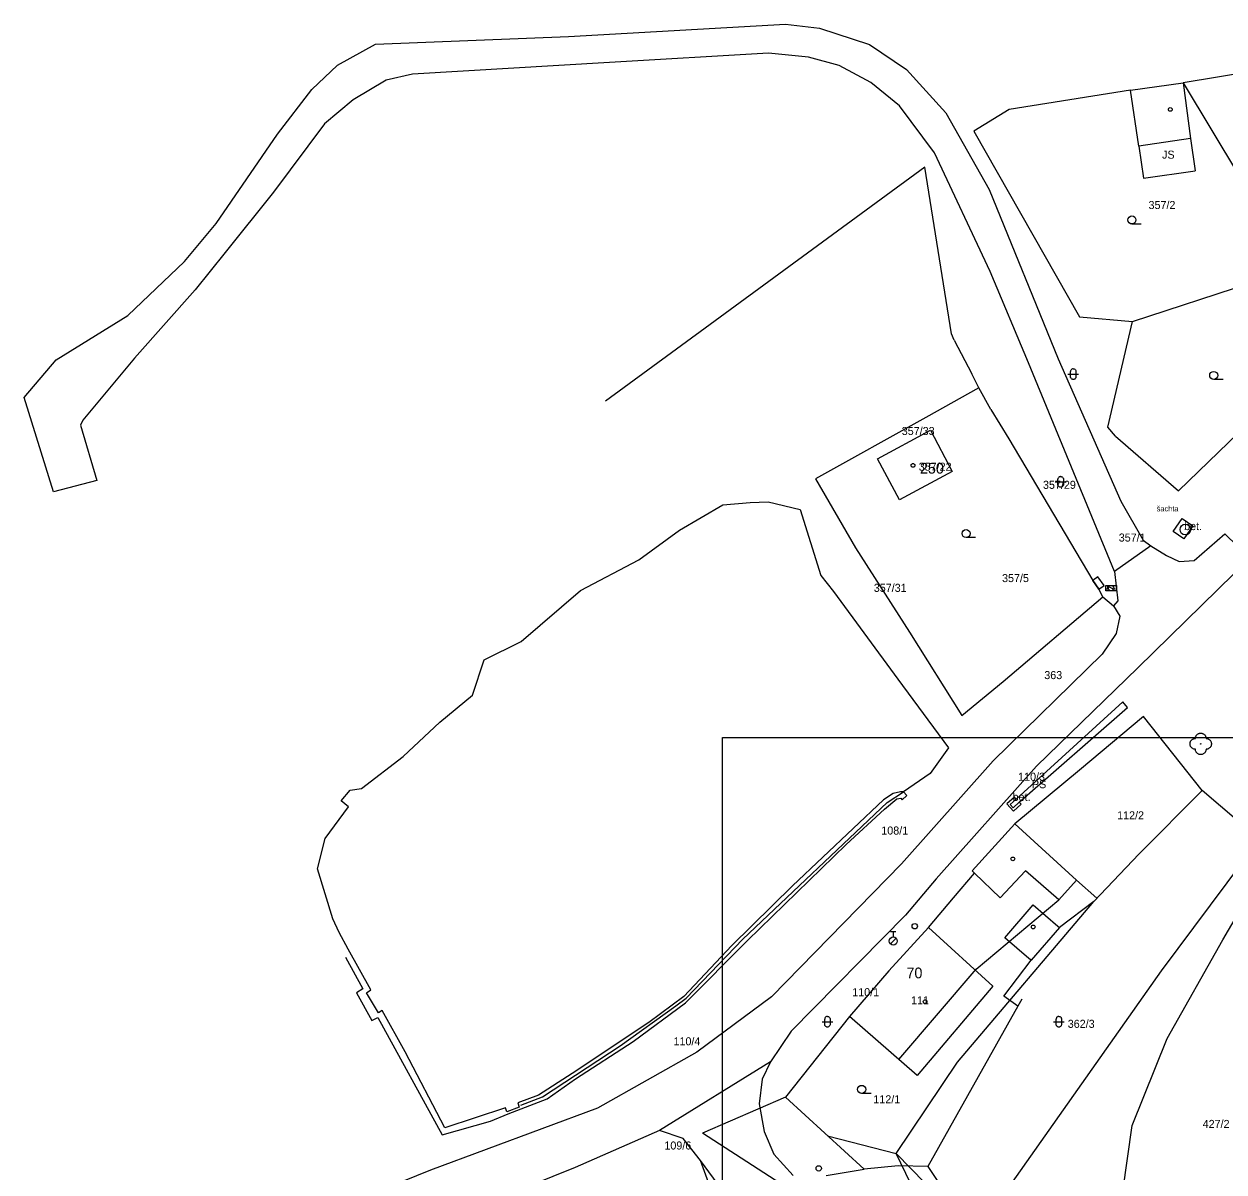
# Model space of a CAD drawing. Extents: x -836615 to -835459, y -1070675 to -1070205.
# Drawn here: x -836568.3 to -836456.3, y -1070319.2 to -1070212.1 of the extents above; entities that cross this region are included whole.
import ezdxf

# ---------------------------------------------------------------- set-up
doc = ezdxf.new("R2010")
doc.units = 0
for name, color, linetype in [('BodPole_body', 7, 'Continuous'), ('Budovy_hranice', 7, 'Continuous'), ('Budovy_kody', 7, 'Continuous'), ('Doprava_hranice', 7, 'Continuous'), ('OstPloch_hranice', 7, 'Continuous'), ('OstPloch_kody', 7, 'Continuous'), ('PovrZnIS_body', 7, 'Continuous'), ('PovrZnIS_hranice', 7, 'Continuous'), ('RuianAdr_popis', 7, 'Continuous'), ('RuianPar_popis', 7, 'Continuous'), ('Stavby_hr_stav', 7, 'Continuous'), ('Stavby_kody', 7, 'Continuous'), ('Stavby_linie', 7, 'Continuous'), ('Stavby_popis', 7, 'Continuous'), ('Vodstvo_hranice', 7, 'Continuous'), ('Zelen_body', 7, 'Continuous')]:
    doc.layers.add(name, color=color, linetype=linetype)

msp = doc.modelspace()

# ---------------------------------------------------------------- linework, layer by layer
at = {"layer": 'BodPole_body'}
msp.add_lwpolyline([(-836503.12, -1070278.67), (-836206.12, -1070278.67), (-836206.12, -1070488.67), (-836503.12, -1070488.67)], close=True, dxfattribs=at)
at = {"layer": 'Budovy_hranice'}
for p, q in [((-836475.84, -1070286.72), (-836479.82, -1070291.11)), ((-836487.6, -1070300.42), (-836491.27, -1070304.7))]:
    msp.add_line(p, q, dxfattribs=at)
for points in [[(-836460.13, -1070217.59), (-836459.42, -1070222.78), (-836464.25, -1070223.5), (-836465.02, -1070218.27), (-836460.13, -1070217.59)], [(-836481.66, -1070253.86), (-836486.58, -1070256.5), (-836488.64, -1070252.68), (-836483.69, -1070250.01), (-836481.66, -1070253.86)], [(-836475.84, -1070286.72), (-836470.06, -1070291.96), (-836471.71, -1070293.81), (-836474.82, -1070291.1), (-836477.18, -1070293.62), (-836479.59, -1070291.33), (-836479.82, -1070291.11)], [(-836474.31, -1070299.45), (-836474.52, -1070299.27), (-836476.76, -1070297.35), (-836474.12, -1070294.28), (-836471.8, -1070296.28), (-836471.67, -1070296.39), (-836474.31, -1070299.45)], [(-836487.6, -1070300.42), (-836483.87, -1070296.4), (-836477.87, -1070301.86), (-836484.93, -1070310.21), (-836491.27, -1070304.7)]]:
    msp.add_lwpolyline(points, dxfattribs=at)
at = {"layer": 'Budovy_kody'}
for p, q in [((-836470.06, -1070291.96), (-836468.16, -1070293.65)), ((-836497.22, -1070312.21), (-836504.98, -1070315.57))]:
    msp.add_line(p, q, dxfattribs=at)
for points in [[(-836493.32, -1070315.82), (-836486.89, -1070317.46), (-836481.18, -1070308.95), (-836468.46, -1070293.96)], [(-836428.56, -1070366.77), (-836395.84, -1070391.08), (-836420.45, -1070375.43), (-836435.19, -1070364.96), (-836454.22, -1070349.64), (-836469.26, -1070337.57), (-836482.9, -1070325.77), (-836486.89, -1070317.46), (-836480.18, -1070324.33), (-836464.23, -1070338.22), (-836436.21, -1070293.95), (-836419.72, -1070300.08)], [(-836486.64, -1070308.7), (-836479.43, -1070300.28), (-836471.71, -1070293.81)], [(-836395.84, -1070391.08), (-836432.08, -1070371.33), (-836463.95, -1070348.14), (-836486.49, -1070329.05), (-836494.06, -1070322.64), (-836504.98, -1070315.57)]]:
    msp.add_lwpolyline(points, dxfattribs=at)
for centre in [(-836461.32, -1070220.08), (-836485.33, -1070253.28), (-836476.01, -1070289.99), (-836474.11, -1070296.34), (-836484.2, -1070303.31)]:
    msp.add_circle(centre, 0.175, dxfattribs=at)
at = {"layer": 'Doprava_hranice'}
for points in [[(-836565.55, -1070255.75), (-836568.29, -1070246.94), (-836565.3, -1070243.45), (-836558.59, -1070239.29), (-836553.32, -1070234.26), (-836550.36, -1070230.73), (-836544.63, -1070222.38), (-836541.42, -1070218.21), (-836539.02, -1070215.95), (-836535.5, -1070213.99), (-836517.48, -1070213.29), (-836497.22, -1070212.11), (-836494.05, -1070212.5), (-836489.39, -1070214.02), (-836485.93, -1070216.36), (-836482.28, -1070220.4), (-836478.23, -1070227.56), (-836471.79, -1070243.33), (-836465.92, -1070256.62), (-836463.85, -1070260.25), (-836463.13, -1070260.78)], [(-836466.54, -1070263.19), (-836474.56, -1070243.73), (-836478.12, -1070235.21), (-836483.33, -1070224.14), (-836486.58, -1070219.75), (-836489.27, -1070217.57), (-836492.22, -1070215.97), (-836495.08, -1070215.2), (-836498.82, -1070214.84), (-836513.64, -1070215.7), (-836532.05, -1070216.8), (-836534.5, -1070217.36), (-836537.57, -1070219.18), (-836540.24, -1070221.43), (-836545, -1070227.8), (-836549.52, -1070233.43), (-836552.32, -1070236.92), (-836557.98, -1070243.27), (-836562.8, -1070249.08), (-836563.01, -1070249.54), (-836561.48, -1070254.69), (-836565.55, -1070255.75)], [(-836463.13, -1070260.78), (-836461.66, -1070261.68), (-836460.5, -1070262.24), (-836459.09, -1070262.17), (-836456.22, -1070259.67), (-836453.89, -1070261.93), (-836464.34, -1070272.16), (-836473.79, -1070281.33)], [(-836463.13, -1070260.78), (-836466.54, -1070263.19), (-836466.2, -1070265.91), (-836466.63, -1070266.39), (-836466.02, -1070267.34), (-836466.37, -1070268.96), (-836467.68, -1070270.88), (-836477.85, -1070280.85), (-836486.39, -1070290.44)], [(-836473.79, -1070281.33), (-836483.18, -1070291.85), (-836486.04, -1070295.25), (-836496.69, -1070306.07), (-836498.64, -1070308.92), (-836508.98, -1070315.34), (-836516.87, -1070318.79), (-836525.05, -1070322.08), (-836528.75, -1070323.23)], [(-836486.39, -1070290.44), (-836498.54, -1070302.85), (-836505.49, -1070308.01), (-836514.78, -1070313.23), (-836530.36, -1070319.04), (-836537.03, -1070321.73), (-836555.38, -1070326.29), (-836561.14, -1070327.96), (-836562.04, -1070328.06)], [(-836498.64, -1070308.92), (-836499.4, -1070310.53), (-836499.69, -1070312.83), (-836499.23, -1070315.41), (-836498.31, -1070317.53), (-836496.52, -1070319.54)], [(-836536.4, -1070368.21), (-836533.17, -1070355.68), (-836529.95, -1070350.14), (-836526.64, -1070346.09), (-836522.06, -1070342.08), (-836518.27, -1070339.72), (-836511.7, -1070337.08), (-836507.28, -1070334.68), (-836504.64, -1070331.81), (-836503.25, -1070329.28), (-836502.09, -1070325.77), (-836501.89, -1070323.62), (-836502.72, -1070321.42), (-836505.15, -1070318.12), (-836506.77, -1070316.06), (-836508.98, -1070315.34)], [(-836541.58, -1070350.39), (-836544.34, -1070349.63), (-836547.79, -1070346.93), (-836549.07, -1070344.38), (-836548.75, -1070338.43), (-836546.32, -1070335.63), (-836537.04, -1070331.76), (-836528.76, -1070329.97), (-836518.57, -1070326.72), (-836515.72, -1070324.62), (-836506.05, -1070328.35), (-836503.77, -1070324.55), (-836503.82, -1070321.79), (-836505.15, -1070318.12)]]:
    msp.add_lwpolyline(points, dxfattribs=at)
at = {"layer": 'OstPloch_hranice'}
for p, q in [((-836467.63, -1070265.54), (-836466.63, -1070266.39)), ((-836493.44, -1070319.52), (-836489.89, -1070318.94))]:
    msp.add_line(p, q, dxfattribs=at)
for points in [[(-836459.22, -1070258.92), (-836460.06, -1070260.14), (-836461.05, -1070259.46), (-836460.21, -1070258.24), (-836459.22, -1070258.92)], [(-836356.62, -1070406.87), (-836370.19, -1070399.44), (-836385.43, -1070392.2), (-836396.38, -1070386.03), (-836404.41, -1070381.11), (-836409.87, -1070376.61), (-836425.28, -1070363.93), (-836449.03, -1070345.44), (-836455, -1070340), (-836462.64, -1070329.11), (-836464.81, -1070325.47), (-836465.74, -1070321.03), (-836464.89, -1070314.87), (-836461.62, -1070306.74), (-836456.41, -1070297.54), (-836450.95, -1070288.2), (-836447.03, -1070272.79), (-836441.38, -1070260.76)]]:
    msp.add_lwpolyline(points, dxfattribs=at)
at = {"layer": 'OstPloch_kody'}
for p, q in [((-836464.03, -1070230.77), (-836464.9, -1070230.77)), ((-836470.62, -1070245.02), (-836470.62, -1070244.52)), ((-836470.12, -1070244.52), (-836470.12, -1070245.02)), ((-836470.87, -1070244.77), (-836469.87, -1070244.77)), ((-836456.4, -1070245.27), (-836457.27, -1070245.27)), ((-836472.05, -1070254.82), (-836471.05, -1070254.82)), ((-836471.8, -1070255.07), (-836471.8, -1070254.57)), ((-836471.3, -1070254.57), (-836471.3, -1070255.07)), ((-836479.51, -1070260.02), (-836480.38, -1070260.02)), ((-836493.82, -1070305.18), (-836492.82, -1070305.18)), ((-836493.57, -1070305.43), (-836493.57, -1070304.93)), ((-836493.07, -1070304.93), (-836493.07, -1070305.43)), ((-836472.22, -1070305.18), (-836471.22, -1070305.18)), ((-836471.97, -1070305.43), (-836471.97, -1070304.93)), ((-836471.47, -1070304.93), (-836471.47, -1070305.43)), ((-836489.24, -1070311.87), (-836490.12, -1070311.87))]:
    msp.add_line(p, q, dxfattribs=at)
for points in [[(-836470.37, -1070244.27), (-836470.42, -1070244.27), (-836470.46, -1070244.29), (-836470.51, -1070244.31), (-836470.55, -1070244.34), (-836470.58, -1070244.38), (-836470.6, -1070244.43), (-836470.62, -1070244.47), (-836470.62, -1070244.52)], [(-836470.37, -1070244.27), (-836470.32, -1070244.27), (-836470.28, -1070244.29), (-836470.23, -1070244.31), (-836470.19, -1070244.34), (-836470.16, -1070244.38), (-836470.14, -1070244.43), (-836470.12, -1070244.47), (-836470.12, -1070244.52)], [(-836470.37, -1070245.27), (-836470.42, -1070245.27), (-836470.46, -1070245.25), (-836470.51, -1070245.23), (-836470.55, -1070245.2), (-836470.58, -1070245.16), (-836470.6, -1070245.11), (-836470.62, -1070245.07), (-836470.62, -1070245.02)], [(-836470.12, -1070245.02), (-836470.12, -1070245.07), (-836470.14, -1070245.11), (-836470.16, -1070245.16), (-836470.19, -1070245.2), (-836470.23, -1070245.23), (-836470.28, -1070245.25), (-836470.32, -1070245.27), (-836470.37, -1070245.27)], [(-836471.55, -1070254.32), (-836471.6, -1070254.32), (-836471.64, -1070254.34), (-836471.69, -1070254.36), (-836471.73, -1070254.39), (-836471.76, -1070254.43), (-836471.78, -1070254.48), (-836471.8, -1070254.52), (-836471.8, -1070254.57)], [(-836471.55, -1070254.32), (-836471.5, -1070254.32), (-836471.46, -1070254.34), (-836471.41, -1070254.36), (-836471.37, -1070254.39), (-836471.34, -1070254.43), (-836471.32, -1070254.48), (-836471.3, -1070254.52), (-836471.3, -1070254.57)], [(-836471.55, -1070255.32), (-836471.6, -1070255.32), (-836471.64, -1070255.3), (-836471.69, -1070255.28), (-836471.73, -1070255.25), (-836471.76, -1070255.21), (-836471.78, -1070255.16), (-836471.8, -1070255.12), (-836471.8, -1070255.07)], [(-836471.3, -1070255.07), (-836471.3, -1070255.12), (-836471.32, -1070255.16), (-836471.34, -1070255.21), (-836471.37, -1070255.25), (-836471.41, -1070255.28), (-836471.46, -1070255.3), (-836471.5, -1070255.32), (-836471.55, -1070255.32)], [(-836493.32, -1070304.68), (-836493.37, -1070304.68), (-836493.41, -1070304.7), (-836493.46, -1070304.72), (-836493.5, -1070304.75), (-836493.53, -1070304.79), (-836493.55, -1070304.84), (-836493.57, -1070304.88), (-836493.57, -1070304.93)], [(-836493.32, -1070304.68), (-836493.27, -1070304.68), (-836493.23, -1070304.7), (-836493.18, -1070304.72), (-836493.14, -1070304.75), (-836493.11, -1070304.79), (-836493.09, -1070304.84), (-836493.07, -1070304.88), (-836493.07, -1070304.93)], [(-836471.72, -1070304.68), (-836471.77, -1070304.68), (-836471.81, -1070304.7), (-836471.86, -1070304.72), (-836471.9, -1070304.75), (-836471.93, -1070304.79), (-836471.95, -1070304.84), (-836471.97, -1070304.88), (-836471.97, -1070304.93)], [(-836471.72, -1070304.68), (-836471.67, -1070304.68), (-836471.63, -1070304.7), (-836471.58, -1070304.72), (-836471.54, -1070304.75), (-836471.51, -1070304.79), (-836471.49, -1070304.84), (-836471.47, -1070304.88), (-836471.47, -1070304.93)], [(-836493.32, -1070305.68), (-836493.37, -1070305.68), (-836493.41, -1070305.66), (-836493.46, -1070305.64), (-836493.5, -1070305.61), (-836493.53, -1070305.57), (-836493.55, -1070305.52), (-836493.57, -1070305.48), (-836493.57, -1070305.43)], [(-836493.07, -1070305.43), (-836493.07, -1070305.48), (-836493.09, -1070305.52), (-836493.11, -1070305.57), (-836493.14, -1070305.61), (-836493.18, -1070305.64), (-836493.23, -1070305.66), (-836493.27, -1070305.68), (-836493.32, -1070305.68)], [(-836471.72, -1070305.68), (-836471.77, -1070305.68), (-836471.81, -1070305.66), (-836471.86, -1070305.64), (-836471.9, -1070305.61), (-836471.93, -1070305.57), (-836471.95, -1070305.52), (-836471.97, -1070305.48), (-836471.97, -1070305.43)], [(-836471.47, -1070305.43), (-836471.47, -1070305.48), (-836471.49, -1070305.52), (-836471.51, -1070305.57), (-836471.54, -1070305.61), (-836471.58, -1070305.64), (-836471.63, -1070305.66), (-836471.67, -1070305.68), (-836471.72, -1070305.68)]]:
    msp.add_lwpolyline(points, dxfattribs=at)
for centre in [(-836464.9, -1070230.39), (-836457.27, -1070244.89), (-836480.38, -1070259.64), (-836490.12, -1070311.49)]:
    msp.add_ellipse(centre, major_axis=(0.375, 0), ratio=0.999999, dxfattribs=at)
at = {"layer": 'PovrZnIS_body'}
for p, q in [((-836467.35, -1070264.98), (-836467.35, -1070264.48)), ((-836467.35, -1070264.48), (-836466.35, -1070264.48)), ((-836467.27, -1070264.81), (-836467.16, -1070264.81)), ((-836467.16, -1070264.81), (-836467.16, -1070264.56)), ((-836467.16, -1070264.56), (-836466.66, -1070264.81)), ((-836466.66, -1070264.81), (-836466.42, -1070264.81)), ((-836466.35, -1070264.48), (-836466.35, -1070264.98)), ((-836466.35, -1070264.98), (-836467.35, -1070264.98)), ((-836487.42, -1070296.77), (-836486.92, -1070296.77)), ((-836487.17, -1070296.77), (-836487.17, -1070297.27)), ((-836486.9, -1070297.38), (-836487.44, -1070297.92))]:
    msp.add_line(p, q, dxfattribs=at)
for centre, radius in [((-836459.91, -1070259.27), 0.5), ((-836466.85, -1070264.73), 0.25), ((-836485.17, -1070296.27), 0.25), ((-836487.17, -1070297.65), 0.375), ((-836494.13, -1070318.86), 0.25)]:
    msp.add_circle(centre, radius, dxfattribs=at)
at = {"layer": 'PovrZnIS_hranice'}
msp.add_lwpolyline([(-836467.99, -1070264.84), (-836467.5, -1070264.5), (-836468.07, -1070263.68), (-836468.56, -1070264.02), (-836467.99, -1070264.84)], dxfattribs=at)
at = {"layer": 'Stavby_hr_stav'}
msp.add_line((-836459.42, -1070222.78), (-836459, -1070225.8), dxfattribs=at)
for points in [[(-836464.25, -1070223.5), (-836463.81, -1070226.48), (-836459, -1070225.8)], [(-836475.41, -1070284.71), (-836465.3, -1070275.87), (-836465.76, -1070275.33), (-836475.69, -1070284.41)], [(-836475.86, -1070284.22), (-836476.56, -1070284.86), (-836475.94, -1070285.54), (-836475.24, -1070284.9), (-836475.41, -1070284.71), (-836475.98, -1070285.22), (-836476.25, -1070284.92), (-836475.69, -1070284.41), (-836475.86, -1070284.22)]]:
    msp.add_lwpolyline(points, dxfattribs=at)
at = {"layer": 'Stavby_linie'}
for p, q in [((-836464.85, -1070239.86), (-836449.69, -1070234.92)), ((-836469.78, -1070239.43), (-836464.85, -1070239.86)), ((-836481.49, -1070241.59), (-836479.85, -1070244.75)), ((-836479.18, -1070246.06), (-836484.13, -1070248.82)), ((-836478.06, -1070248.07), (-836476.39, -1070250.81)), ((-836476.39, -1070250.81), (-836468.56, -1070264.02)), ((-836466.44, -1070250.56), (-836460.54, -1070255.66)), ((-836463.82, -1070276.71), (-836469.8, -1070281.7)), ((-836458.36, -1070283.6), (-836463.82, -1070276.71)), ((-836469.8, -1070281.7), (-836475.84, -1070286.72)), ((-836481.56, -1070293.61), (-836479.59, -1070291.33)), ((-836483.87, -1070296.4), (-836481.56, -1070293.61)), ((-836476.86, -1070302.79), (-836474.31, -1070299.45)), ((-836475.56, -1070303.74), (-836476.86, -1070302.79))]:
    msp.add_line(p, q, dxfattribs=at)
for points in [[(-836439.81, -1070215.21), (-836443.91, -1070214.91), (-836460.13, -1070217.59), (-836449.69, -1070234.92)], [(-836465.02, -1070218.27), (-836476.36, -1070220.08), (-836479.66, -1070222.11), (-836469.78, -1070239.43)], [(-836481.49, -1070241.59), (-836481.74, -1070241), (-836484.22, -1070225.45), (-836507.86, -1070242.77), (-836514.01, -1070247.28)], [(-836460.54, -1070255.66), (-836450.32, -1070245.76), (-836439.91, -1070235.75)], [(-836466.44, -1070250.56), (-836467.14, -1070249.72), (-836464.85, -1070239.86)], [(-836478.06, -1070248.07), (-836479.18, -1070246.06), (-836479.85, -1070244.75)], [(-836484.13, -1070248.82), (-836494.44, -1070254.55), (-836490.71, -1070260.96)], [(-836490.71, -1070260.96), (-836485.67, -1070268.85), (-836480.77, -1070276.62), (-836476.92, -1070273.45)], [(-836476.92, -1070273.45), (-836467.63, -1070265.54), (-836467.99, -1070264.84), (-836468.56, -1070264.02)], [(-836521.92, -1070312.95), (-836519.9, -1070312.2), (-836512.67, -1070307.44), (-836507.45, -1070303.71), (-836506.51, -1070302.98), (-836501.2, -1070297.48), (-836487.74, -1070284.74), (-836486.21, -1070283.75)], [(-836483.95, -1070318.68), (-836480.18, -1070324.33), (-836477.38, -1070322.05), (-836462.13, -1070300.43), (-836452.98, -1070288.18), (-836458.36, -1070283.6)], [(-836458.36, -1070283.6), (-836464.21, -1070289.51), (-836468.46, -1070293.96), (-836471.67, -1070296.39)], [(-836475.18, -1070303.07), (-836475.56, -1070303.74), (-836483.95, -1070318.68)], [(-836491.27, -1070304.7), (-836497.22, -1070312.21), (-836489.89, -1070318.94)], [(-836483.95, -1070318.68), (-836486.71, -1070318.63), (-836489.89, -1070318.94)]]:
    msp.add_lwpolyline(points, dxfattribs=at)
at = {"layer": 'Vodstvo_hranice'}
for points in [[(-836486.21, -1070283.75), (-836486.51, -1070283.72), (-836487.17, -1070283.89), (-836488.08, -1070284.48), (-836496.59, -1070292.51), (-836502.23, -1070298.08), (-836506.71, -1070302.82), (-836509.99, -1070305.26), (-836517.14, -1070310.02), (-836520.29, -1070312.03), (-836522.22, -1070312.76), (-836522.07, -1070313.16), (-836523.23, -1070313.58), (-836523.35, -1070313.2), (-836529.02, -1070315.07), (-836532.73, -1070307.98), (-836534.86, -1070304.13), (-836535.22, -1070304.34), (-836536.32, -1070302.47), (-836535.91, -1070302.21), (-836538.03, -1070298.42), (-836538.87, -1070296.86), (-836539.46, -1070295.59), (-836540.9, -1070290.92), (-836540.19, -1070288.1), (-836538.02, -1070285.12), (-836538.7, -1070284.57), (-836537.84, -1070283.58), (-836536.78, -1070283.42), (-836532.91, -1070280.44), (-836529.5, -1070277.24), (-836526.44, -1070274.72), (-836525.34, -1070271.43), (-836521.88, -1070269.71), (-836516.37, -1070264.96), (-836510.93, -1070262.08), (-836507.11, -1070259.33), (-836503.08, -1070256.96), (-836500.52, -1070256.76), (-836498.86, -1070256.68), (-836495.87, -1070257.41), (-836493.93, -1070263.56), (-836492.75, -1070265.06), (-836486.76, -1070273.24), (-836482.01, -1070279.63), (-836483.74, -1070282.01), (-836486.21, -1070283.75)], [(-836538.28, -1070299.17), (-836536.67, -1070302.12), (-836537.27, -1070302.49), (-836535.82, -1070305.08), (-836535.28, -1070304.8), (-836529.27, -1070315.73), (-836524.75, -1070314.46), (-836523.12, -1070313.78), (-836521.89, -1070313.32), (-836519.48, -1070312.36), (-836516.81, -1070310.51), (-836511.44, -1070307.01), (-836506.56, -1070303.42), (-836500.78, -1070297.61), (-836491.56, -1070288.65), (-836487.98, -1070285.34), (-836486.83, -1070284.4), (-836486.48, -1070284.32), (-836486.34, -1070284.49), (-836485.89, -1070284.09), (-836486.21, -1070283.75)]]:
    msp.add_lwpolyline(points, dxfattribs=at)
at = {"layer": 'Zelen_body'}
msp.add_line((-836458.48, -1070279.26), (-836458.48, -1070279.26), dxfattribs=at)
for points in [[(-836458.98, -1070278.76), (-836458.98, -1070278.71), (-836458.97, -1070278.66), (-836458.96, -1070278.61), (-836458.94, -1070278.56), (-836458.92, -1070278.52), (-836458.89, -1070278.47), (-836458.85, -1070278.43), (-836458.81, -1070278.39), (-836458.77, -1070278.35), (-836458.72, -1070278.32), (-836458.68, -1070278.3), (-836458.63, -1070278.28), (-836458.58, -1070278.27), (-836458.53, -1070278.26), (-836458.48, -1070278.26), (-836458.43, -1070278.26), (-836458.38, -1070278.27), (-836458.33, -1070278.28), (-836458.28, -1070278.3), (-836458.24, -1070278.32), (-836458.19, -1070278.35), (-836458.15, -1070278.39), (-836458.11, -1070278.43), (-836458.07, -1070278.47), (-836458.04, -1070278.52), (-836458.02, -1070278.56), (-836458, -1070278.61), (-836457.99, -1070278.66), (-836457.98, -1070278.71), (-836457.98, -1070278.76)], [(-836458.98, -1070279.76), (-836459.03, -1070279.76), (-836459.08, -1070279.75), (-836459.13, -1070279.74), (-836459.18, -1070279.72), (-836459.22, -1070279.7), (-836459.27, -1070279.67), (-836459.31, -1070279.63), (-836459.35, -1070279.59), (-836459.39, -1070279.55), (-836459.42, -1070279.5), (-836459.44, -1070279.46), (-836459.46, -1070279.41), (-836459.47, -1070279.36), (-836459.48, -1070279.31), (-836459.48, -1070279.26), (-836459.48, -1070279.21), (-836459.47, -1070279.16), (-836459.46, -1070279.11), (-836459.44, -1070279.06), (-836459.42, -1070279.02), (-836459.39, -1070278.97), (-836459.35, -1070278.93), (-836459.31, -1070278.89), (-836459.27, -1070278.85), (-836459.22, -1070278.82), (-836459.18, -1070278.8), (-836459.13, -1070278.78), (-836459.08, -1070278.77), (-836459.03, -1070278.76), (-836458.98, -1070278.76)], [(-836457.98, -1070278.76), (-836457.93, -1070278.76), (-836457.88, -1070278.77), (-836457.83, -1070278.78), (-836457.78, -1070278.8), (-836457.74, -1070278.82), (-836457.69, -1070278.85), (-836457.65, -1070278.89), (-836457.61, -1070278.93), (-836457.57, -1070278.97), (-836457.54, -1070279.02), (-836457.52, -1070279.06), (-836457.5, -1070279.11), (-836457.49, -1070279.16), (-836457.48, -1070279.21), (-836457.48, -1070279.26), (-836457.48, -1070279.31), (-836457.49, -1070279.36), (-836457.5, -1070279.41), (-836457.52, -1070279.46), (-836457.54, -1070279.5), (-836457.57, -1070279.55), (-836457.61, -1070279.59), (-836457.65, -1070279.63), (-836457.69, -1070279.67), (-836457.74, -1070279.7), (-836457.78, -1070279.72), (-836457.83, -1070279.74), (-836457.88, -1070279.75), (-836457.93, -1070279.76), (-836457.98, -1070279.76)], [(-836457.98, -1070279.76), (-836457.98, -1070279.81), (-836457.99, -1070279.86), (-836458, -1070279.91), (-836458.02, -1070279.96), (-836458.04, -1070280), (-836458.07, -1070280.05), (-836458.11, -1070280.09), (-836458.15, -1070280.13), (-836458.19, -1070280.17), (-836458.24, -1070280.2), (-836458.28, -1070280.22), (-836458.33, -1070280.24), (-836458.38, -1070280.25), (-836458.43, -1070280.26), (-836458.48, -1070280.26), (-836458.53, -1070280.26), (-836458.58, -1070280.25), (-836458.63, -1070280.24), (-836458.68, -1070280.22), (-836458.72, -1070280.2), (-836458.77, -1070280.17), (-836458.81, -1070280.13), (-836458.85, -1070280.09), (-836458.89, -1070280.05), (-836458.92, -1070280), (-836458.94, -1070279.96), (-836458.96, -1070279.91), (-836458.97, -1070279.86), (-836458.98, -1070279.81), (-836458.98, -1070279.76)]]:
    msp.add_lwpolyline(points, dxfattribs=at)
msp.add_ellipse((-836458.48, -1070279.26), major_axis=(0.025, 0), ratio=0.999997, dxfattribs=at)

# ---------------------------------------------------------------- texts
at = {"layer": 'RuianAdr_popis'}
for s, p in [('250', (-836484.68, -1070254.05)), ('70', (-836485.94, -1070301.13))]:
    msp.add_text(s, height=1, dxfattribs=at).set_placement(p)
at = {"layer": 'RuianPar_popis'}
for s, p in [('357/2', (-836463.35, -1070229.37)), ('357/33', (-836486.38, -1070250.45)), ('357/22', (-836484.8, -1070253.78)), ('357/29', (-836473.2, -1070255.47)), ('357/1', (-836466.13, -1070260.39)), ('357/5', (-836477.02, -1070264.17)), ('357/31', (-836488.99, -1070265.08)), ('363', (-836473.08, -1070273.22)), ('110/3', (-836475.52, -1070282.7)), ('112/2', (-836466.28, -1070286.3)), ('108/1', (-836488.29, -1070287.72)), ('110/1', (-836491, -1070302.8)), ('111', (-836485.51, -1070303.56)), ('362/3', (-836470.89, -1070305.75)), ('110/4', (-836507.68, -1070307.38)), ('112/1', (-836489.03, -1070312.79)), ('427/2', (-836458.3, -1070315.09)), ('109/6', (-836508.53, -1070317.1))]:
    msp.add_text(s, height=0.75, dxfattribs=at).set_placement(p)
at = {"layer": 'Stavby_kody'}
for s, p in [('JS', (-836462.09, -1070224.67)), ('bet.', (-836460.03, -1070259.32)), ('PS', (-836474.23, -1070283.4)), ('bet.', (-836476.03, -1070284.59))]:
    msp.add_text(s, height=0.75, dxfattribs=at).set_placement(p)
at = {"layer": 'Stavby_popis'}
msp.add_text('šachta', height=0.5, dxfattribs=at).set_placement((-836462.59, -1070257.57))

doc.saveas('drawing.dxf')
